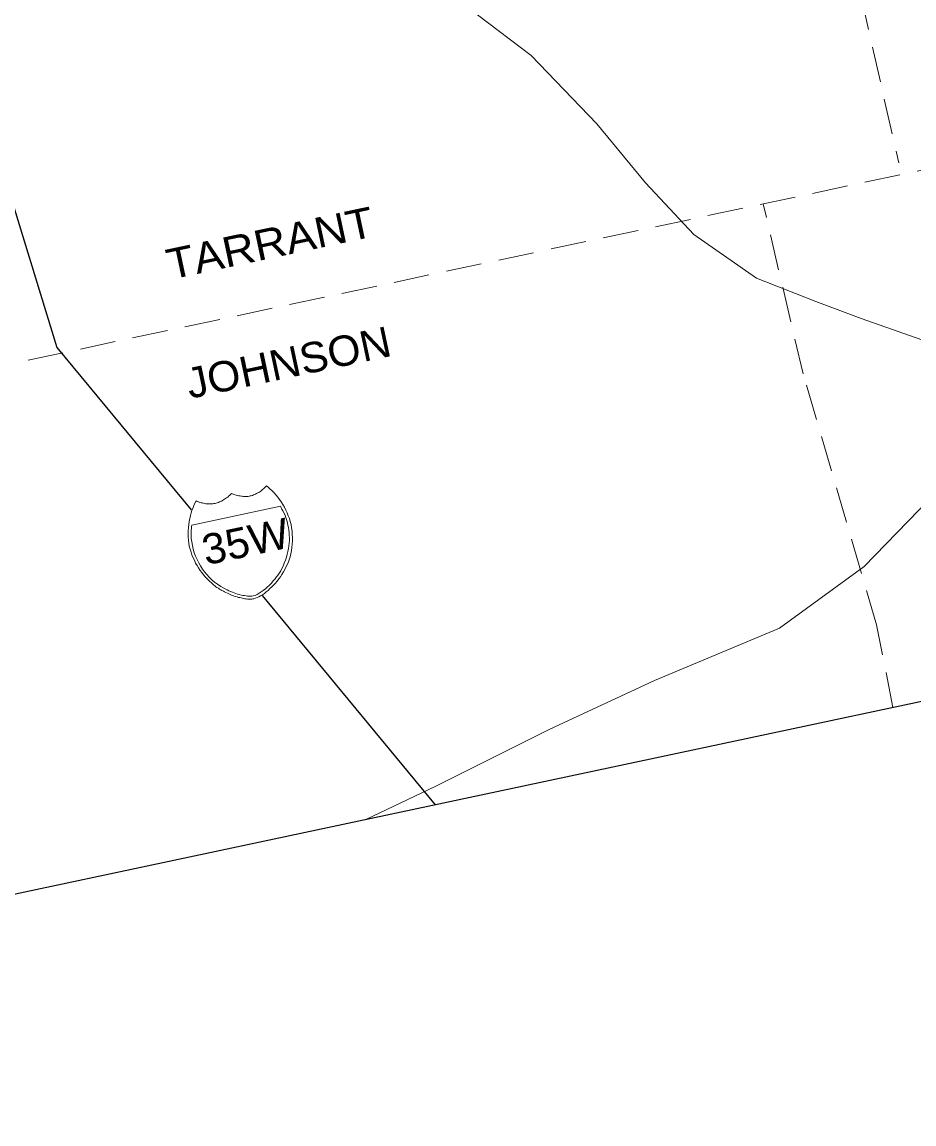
# Model space of a CAD drawing. Extents: x 2357218 to 2371708, y 6973728 to 6980157.
# Drawn here: x 2357522.9 to 2357673, y 6974407.9 to 6974593.4 of the extents above; entities that cross this region are included whole.
import ezdxf

# ---------------------------------------------------------------- set-up
doc = ezdxf.new("R2010")
doc.units = 0
doc.header["$LTSCALE"] = 2
doc.linetypes.add('MEDIUM_DASHED', pattern=[4.5, 3, -1.5])
doc.layers.add('62', color=7, linetype='Continuous', lineweight=13)
doc.layers.add('63', color=7, linetype='Continuous', lineweight=13)

msp = doc.modelspace()

# ---------------------------------------------------------------- linework, layer by layer
at = {"layer": '62', "linetype": 'MEDIUM_DASHED'}
for p, q in [((2357608.391, 6974843.78), (2357670.463, 6974569.716)), ((2357321.423, 6974493.477), (2357761.192, 6974586.953))]:
    msp.add_line(p, q, dxfattribs=at)
at = {"layer": '62', "lineweight": 25}
msp.add_line((2357563.3, 6974496.922), (2357592.436, 6974461.686), dxfattribs=at)
for points in [[(2357242.867, 6974863.05), (2357339.603, 6974407.945), (2357779.37, 6974501.42), (2357682.634, 6974956.528)], [(2357484.401, 6974709.004), (2357495.501, 6974661.441), (2357507.761, 6974607.022), (2357528.73, 6974538.67), (2357551.355, 6974511.341)]]:
    msp.add_lwpolyline(points, dxfattribs=at)
at = {"layer": '62'}
for points in [[(2357711.499, 6974538.57), (2357702.972, 6974539.842), (2357693.168, 6974539.642), (2357675.502, 6974539.523), (2357664.168, 6974543.509), (2357656.491, 6974546.383), (2357646.543, 6974550.319), (2357635.988, 6974557.671), (2357627.86, 6974566.366), (2357619.672, 6974576.31), (2357608.58, 6974587.803), (2357599.534, 6974594.644), (2357592.196, 6974601.778), (2357583.834, 6974610.927), (2357578.923, 6974614.877), (2357569.363, 6974625.866)], [(2357712.856, 6974614.337), (2357709.274, 6974604.465), (2357703.489, 6974586.211), (2357701.445, 6974566.614), (2357701.343, 6974551.94), (2357687.74, 6974535.638), (2357689.697, 6974525.767), (2357675.675, 6974513.172), (2357664.632, 6974501.808), (2357650.419, 6974491.402), (2357629.375, 6974482.602), (2357611.62, 6974474.364), (2357592.404, 6974464.761), (2357580.771, 6974459.205)], [(2357561.902, 6974496.349), (2357561.721, 6974496.335), (2357561.569, 6974496.303), (2357561.388, 6974496.286), (2357561.226, 6974496.298), (2357561.039, 6974496.305), (2357560.854, 6974496.31), (2357560.618, 6974496.331), (2357560.405, 6974496.353), (2357560.212, 6974496.404), (2357560, 6974496.429), (2357559.754, 6974496.49), (2357559.538, 6974496.536), (2357559.299, 6974496.58), (2357559.103, 6974496.65), (2357558.851, 6974496.737), (2357558.608, 6974496.801), (2357558.383, 6974496.89), (2357558.134, 6974496.976), (2357557.906, 6974497.087), (2357557.678, 6974497.176), (2357557.45, 6974497.267), (2357557.217, 6974497.402), (2357556.989, 6974497.492), (2357556.781, 6974497.609), (2357556.546, 6974497.743), (2357556.337, 6974497.859), (2357556.128, 6974497.974), (2357555.936, 6974498.118), (2357555.701, 6974498.252), (2357555.514, 6974498.372), (2357555.343, 6974498.522), (2357555.153, 6974498.665), (2357554.814, 6974498.961), (2357554.438, 6974499.32), (2357554.113, 6974499.663), (2357553.788, 6974500.009), (2357553.457, 6974500.374), (2357553.147, 6974500.745), (2357552.861, 6974501.12), (2357552.612, 6974501.53), (2357552.343, 6974501.932), (2357552.09, 6974502.361), (2357551.899, 6974502.828), (2357551.691, 6974503.266), (2357551.477, 6974503.727), (2357551.335, 6974504.181), (2357551.18, 6974504.7), (2357551.047, 6974505.2), (2357550.986, 6974505.719), (2357550.921, 6974506.234), (2357550.88, 6974506.754), (2357550.859, 6974507.279), (2357550.867, 6974507.787), (2357550.893, 6974508.321), (2357550.943, 6974508.836), (2357550.994, 6974509.354), (2357551.117, 6974509.864), (2357551.219, 6974510.346), (2357551.351, 6974510.809), (2357551.491, 6974511.232), (2357551.672, 6974511.686), (2357551.796, 6974512.076), (2357551.989, 6974512.463), (2357552.188, 6974512.828), (2357552.392, 6974512.735), (2357552.618, 6974512.644), (2357552.841, 6974512.575), (2357553.036, 6974512.524), (2357553.252, 6974512.478), (2357553.446, 6974512.429), (2357553.658, 6974512.404), (2357553.855, 6974512.355), (2357554.038, 6974512.349), (2357554.228, 6974512.319), (2357554.435, 6974512.317), (2357554.616, 6974512.331), (2357554.848, 6974512.337), (2357555.011, 6974512.323), (2357555.187, 6974512.361), (2357555.406, 6974512.408), (2357555.582, 6974512.446), (2357555.758, 6974512.483), (2357555.946, 6974512.568), (2357556.113, 6974512.65), (2357556.284, 6974512.71), (2357556.451, 6974512.792), (2357556.658, 6974512.905), (2357556.827, 6974512.985), (2357556.984, 6974513.112), (2357557.146, 6974513.216), (2357557.325, 6974513.346), (2357557.503, 6974513.476), (2357557.661, 6974513.601), (2357557.814, 6974513.747), (2357557.964, 6974513.917), (2357558.131, 6974514.091), (2357558.335, 6974513.998), (2357558.539, 6974513.902), (2357558.762, 6974513.835), (2357558.955, 6974513.784)], [(2357558.955, 6974513.784), (2357559.152, 6974513.732), (2357559.368, 6974513.686), (2357559.537, 6974513.654), (2357559.753, 6974513.608), (2357559.96, 6974513.605), (2357560.15, 6974513.578), (2357560.335, 6974513.572), (2357560.538, 6974513.591), (2357560.723, 6974513.585), (2357560.932, 6974513.583), (2357561.108, 6974513.62), (2357561.308, 6974513.663), (2357561.482, 6974513.699), (2357561.656, 6974513.737), (2357561.867, 6974513.829), (2357562.013, 6974513.904), (2357562.184, 6974513.965), (2357562.373, 6974514.049), (2357562.558, 6974514.159), (2357562.725, 6974514.24), (2357562.904, 6974514.369), (2357563.066, 6974514.472), (2357563.223, 6974514.597), (2357563.381, 6974514.723), (2357563.538, 6974514.848), (2357563.712, 6974515.002), (2357563.881, 6974515.177), (2357564.031, 6974515.346), (2357564.359, 6974515.094), (2357564.673, 6974514.816), (2357564.989, 6974514.515), (2357565.314, 6974514.17), (2357565.616, 6974513.842), (2357565.924, 6974513.471), (2357566.218, 6974513.073), (2357566.514, 6974512.652), (2357566.792, 6974512.207), (2357567.05, 6974511.755), (2357567.287, 6974511.276), (2357567.501, 6974510.816), (2357567.697, 6974510.328), (2357567.892, 6974509.84), (2357568.023, 6974509.339), (2357568.176, 6974508.841), (2357568.248, 6974508.282), (2357568.342, 6974507.725), (2357568.373, 6974507.157), (2357568.412, 6974506.636), (2357568.438, 6974506.09), (2357568.374, 6974505.524), (2357568.328, 6974504.984), (2357568.254, 6974504.464), (2357568.136, 6974503.931), (2357567.998, 6974503.397), (2357567.828, 6974502.899), (2357567.66, 6974502.381), (2357567.425, 6974501.871), (2357567.181, 6974501.384), (2357566.92, 6974500.888), (2357566.607, 6974500.41), (2357566.387, 6974500.041), (2357566.14, 6974499.69), (2357565.847, 6974499.328), (2357565.573, 6974498.994), (2357565.25, 6974498.673), (2357564.926, 6974498.35), (2357564.621, 6974498.055), (2357564.318, 6974497.761), (2357564.007, 6974497.489), (2357563.689, 6974497.257), (2357563.369, 6974497.03), (2357563.047, 6974496.822), (2357562.755, 6974496.668), (2357562.461, 6974496.538), (2357562.161, 6974496.429), (2357561.902, 6974496.349)]]:
    msp.add_lwpolyline(points, dxfattribs=at)
at = {"layer": '62', "linetype": 'MEDIUM_DASHED'}
msp.add_lwpolyline([(2357669.497, 6974478.065), (2357666.726, 6974491.968), (2357654.36, 6974534.223), (2357647.638, 6974562.817)], dxfattribs=at)
at = {"layer": '62'}
msp.add_lwpolyline([(2357566.373, 6974511.911), (2357551.47, 6974508.742), (2357551.43, 6974508.504), (2357551.401, 6974508.2), (2357551.378, 6974507.874), (2357551.375, 6974507.456), (2357551.359, 6974506.993), (2357551.378, 6974506.469), (2357551.446, 6974505.931), (2357551.575, 6974505.312), (2357551.705, 6974504.72), (2357551.884, 6974504.088), (2357552.098, 6974503.514), (2357552.356, 6974502.947), (2357552.637, 6974502.386), (2357552.93, 6974501.873), (2357553.249, 6974501.343), (2357553.625, 6974500.871), (2357553.997, 6974500.421), (2357554.392, 6974499.976), (2357554.852, 6974499.544), (2357555.305, 6974499.135), (2357555.817, 6974498.785), (2357556.351, 6974498.435), (2357556.876, 6974498.133), (2357557.445, 6974497.842), (2357557.706, 6974497.689), (2357558.003, 6974497.59), (2357558.288, 6974497.444), (2357558.606, 6974497.351), (2357558.884, 6974497.248), (2357559.183, 6974497.13), (2357559.47, 6974497.076), (2357559.767, 6974496.978), (2357560.055, 6974496.922), (2357560.316, 6974496.888), (2357560.605, 6974496.833), (2357560.843, 6974496.791), (2357561.12, 6974496.781), (2357561.35, 6974496.785), (2357561.575, 6974496.81), (2357561.801, 6974496.836), (2357562.106, 6974496.923), (2357562.463, 6974497.066), (2357562.788, 6974497.273), (2357563.156, 6974497.492), (2357563.495, 6974497.723), (2357563.85, 6974498.007), (2357564.179, 6974498.306), (2357564.523, 6974498.631), (2357564.864, 6974498.981), (2357565.177, 6974499.346), (2357565.473, 6974499.684), (2357565.747, 6974500.019), (2357566.022, 6974500.353), (2357566.247, 6974500.7), (2357566.45, 6974501.044), (2357566.574, 6974501.323), (2357566.828, 6974501.861), (2357567.02, 6974502.361), (2357567.213, 6974502.86), (2357567.379, 6974503.378), (2357567.532, 6974503.85), (2357567.64, 6974504.333), (2357567.725, 6974504.787), (2357567.786, 6974505.26), (2357567.85, 6974505.711), (2357567.894, 6974506.156), (2357567.895, 6974506.596), (2357567.866, 6974507.048), (2357567.842, 6974507.481), (2357567.798, 6974507.908), (2357567.73, 6974508.334), (2357567.646, 6974508.728), (2357567.515, 6974509.347), (2357567.36, 6974509.864), (2357567.164, 6974510.354), (2357567.004, 6974510.778), (2357566.81, 6974511.152), (2357566.633, 6974511.437), (2357566.484, 6974511.704)], close=True, dxfattribs=at)
at = {"layer": '63', "linetype": 'MEDIUM_DASHED'}
for p, q in [((2357608.391, 6974843.78), (2357670.463, 6974569.716)), ((2357321.423, 6974493.477), (2357761.192, 6974586.953))]:
    msp.add_line(p, q, dxfattribs=at)
at = {"layer": '63', "lineweight": 25}
msp.add_line((2357563.3, 6974496.922), (2357592.436, 6974461.686), dxfattribs=at)
for points in [[(2357242.867, 6974863.05), (2357339.603, 6974407.945), (2357779.37, 6974501.42), (2357682.634, 6974956.528)], [(2357484.401, 6974709.004), (2357495.501, 6974661.441), (2357507.761, 6974607.022), (2357528.73, 6974538.67), (2357551.355, 6974511.341)]]:
    msp.add_lwpolyline(points, dxfattribs=at)
at = {"layer": '63'}
for points in [[(2357711.499, 6974538.57), (2357702.972, 6974539.842), (2357693.168, 6974539.642), (2357675.502, 6974539.523), (2357664.168, 6974543.509), (2357656.491, 6974546.383), (2357646.543, 6974550.319), (2357635.988, 6974557.671), (2357627.86, 6974566.366), (2357619.672, 6974576.31), (2357608.58, 6974587.803), (2357599.534, 6974594.644), (2357592.196, 6974601.778), (2357583.834, 6974610.927), (2357578.923, 6974614.877), (2357569.363, 6974625.866)], [(2357712.856, 6974614.337), (2357709.274, 6974604.465), (2357703.489, 6974586.211), (2357701.445, 6974566.614), (2357701.343, 6974551.94), (2357687.74, 6974535.638), (2357689.697, 6974525.767), (2357675.675, 6974513.172), (2357664.632, 6974501.808), (2357650.419, 6974491.402), (2357629.375, 6974482.602), (2357611.62, 6974474.364), (2357592.404, 6974464.761), (2357580.771, 6974459.205)], [(2357561.902, 6974496.349), (2357561.721, 6974496.335), (2357561.569, 6974496.303), (2357561.388, 6974496.286), (2357561.226, 6974496.298), (2357561.039, 6974496.305), (2357560.854, 6974496.31), (2357560.618, 6974496.331), (2357560.405, 6974496.353), (2357560.212, 6974496.404), (2357560, 6974496.429), (2357559.754, 6974496.49), (2357559.538, 6974496.536), (2357559.299, 6974496.58), (2357559.103, 6974496.65), (2357558.851, 6974496.737), (2357558.608, 6974496.801), (2357558.383, 6974496.89), (2357558.134, 6974496.976), (2357557.906, 6974497.087), (2357557.678, 6974497.176), (2357557.45, 6974497.267), (2357557.217, 6974497.402), (2357556.989, 6974497.492), (2357556.781, 6974497.609), (2357556.546, 6974497.743), (2357556.337, 6974497.859), (2357556.128, 6974497.974), (2357555.936, 6974498.118), (2357555.701, 6974498.252), (2357555.514, 6974498.372), (2357555.343, 6974498.522), (2357555.153, 6974498.665), (2357554.814, 6974498.961), (2357554.438, 6974499.32), (2357554.113, 6974499.663), (2357553.788, 6974500.009), (2357553.457, 6974500.374), (2357553.147, 6974500.745), (2357552.861, 6974501.12), (2357552.612, 6974501.53), (2357552.343, 6974501.932), (2357552.09, 6974502.361), (2357551.899, 6974502.828), (2357551.691, 6974503.266), (2357551.477, 6974503.727), (2357551.335, 6974504.181), (2357551.18, 6974504.7), (2357551.047, 6974505.2), (2357550.986, 6974505.719), (2357550.921, 6974506.234), (2357550.88, 6974506.754), (2357550.859, 6974507.279), (2357550.867, 6974507.787), (2357550.893, 6974508.321), (2357550.943, 6974508.836), (2357550.994, 6974509.354), (2357551.117, 6974509.864), (2357551.219, 6974510.346), (2357551.351, 6974510.809), (2357551.491, 6974511.232), (2357551.672, 6974511.686), (2357551.796, 6974512.076), (2357551.989, 6974512.463), (2357552.188, 6974512.828), (2357552.392, 6974512.735), (2357552.618, 6974512.644), (2357552.841, 6974512.575), (2357553.036, 6974512.524), (2357553.252, 6974512.478), (2357553.446, 6974512.429), (2357553.658, 6974512.404), (2357553.855, 6974512.355), (2357554.038, 6974512.349), (2357554.228, 6974512.319), (2357554.435, 6974512.317), (2357554.616, 6974512.331), (2357554.848, 6974512.337), (2357555.011, 6974512.323), (2357555.187, 6974512.361), (2357555.406, 6974512.408), (2357555.582, 6974512.446), (2357555.758, 6974512.483), (2357555.946, 6974512.568), (2357556.113, 6974512.65), (2357556.284, 6974512.71), (2357556.451, 6974512.792), (2357556.658, 6974512.905), (2357556.827, 6974512.985), (2357556.984, 6974513.112), (2357557.146, 6974513.216), (2357557.325, 6974513.346), (2357557.503, 6974513.476), (2357557.661, 6974513.601), (2357557.814, 6974513.747), (2357557.964, 6974513.917), (2357558.131, 6974514.091), (2357558.335, 6974513.998), (2357558.539, 6974513.902), (2357558.762, 6974513.835), (2357558.955, 6974513.784)], [(2357558.955, 6974513.784), (2357559.152, 6974513.732), (2357559.368, 6974513.686), (2357559.537, 6974513.654), (2357559.753, 6974513.608), (2357559.96, 6974513.605), (2357560.15, 6974513.578), (2357560.335, 6974513.572), (2357560.538, 6974513.591), (2357560.723, 6974513.585), (2357560.932, 6974513.583), (2357561.108, 6974513.62), (2357561.308, 6974513.663), (2357561.482, 6974513.699), (2357561.656, 6974513.737), (2357561.867, 6974513.829), (2357562.013, 6974513.904), (2357562.184, 6974513.965), (2357562.373, 6974514.049), (2357562.558, 6974514.159), (2357562.725, 6974514.24), (2357562.904, 6974514.369), (2357563.066, 6974514.472), (2357563.223, 6974514.597), (2357563.381, 6974514.723), (2357563.538, 6974514.848), (2357563.712, 6974515.002), (2357563.881, 6974515.177), (2357564.031, 6974515.346), (2357564.359, 6974515.094), (2357564.673, 6974514.816), (2357564.989, 6974514.515), (2357565.314, 6974514.17), (2357565.616, 6974513.842), (2357565.924, 6974513.471), (2357566.218, 6974513.073), (2357566.514, 6974512.652), (2357566.792, 6974512.207), (2357567.05, 6974511.755), (2357567.287, 6974511.276), (2357567.501, 6974510.816), (2357567.697, 6974510.328), (2357567.892, 6974509.84), (2357568.023, 6974509.339), (2357568.176, 6974508.841), (2357568.248, 6974508.282), (2357568.342, 6974507.725), (2357568.373, 6974507.157), (2357568.412, 6974506.636), (2357568.438, 6974506.09), (2357568.374, 6974505.524), (2357568.328, 6974504.984), (2357568.254, 6974504.464), (2357568.136, 6974503.931), (2357567.998, 6974503.397), (2357567.828, 6974502.899), (2357567.66, 6974502.381), (2357567.425, 6974501.871), (2357567.181, 6974501.384), (2357566.92, 6974500.888), (2357566.607, 6974500.41), (2357566.387, 6974500.041), (2357566.14, 6974499.69), (2357565.847, 6974499.328), (2357565.573, 6974498.994), (2357565.25, 6974498.673), (2357564.926, 6974498.35), (2357564.621, 6974498.055), (2357564.318, 6974497.761), (2357564.007, 6974497.489), (2357563.689, 6974497.257), (2357563.369, 6974497.03), (2357563.047, 6974496.822), (2357562.755, 6974496.668), (2357562.461, 6974496.538), (2357562.161, 6974496.429), (2357561.902, 6974496.349)]]:
    msp.add_lwpolyline(points, dxfattribs=at)
at = {"layer": '63', "linetype": 'MEDIUM_DASHED'}
msp.add_lwpolyline([(2357669.497, 6974478.065), (2357666.726, 6974491.968), (2357654.36, 6974534.223), (2357647.638, 6974562.817)], dxfattribs=at)
at = {"layer": '63'}
msp.add_lwpolyline([(2357566.373, 6974511.911), (2357551.47, 6974508.742), (2357551.43, 6974508.504), (2357551.401, 6974508.2), (2357551.378, 6974507.874), (2357551.375, 6974507.456), (2357551.359, 6974506.993), (2357551.378, 6974506.469), (2357551.446, 6974505.931), (2357551.575, 6974505.312), (2357551.705, 6974504.72), (2357551.884, 6974504.088), (2357552.098, 6974503.514), (2357552.356, 6974502.947), (2357552.637, 6974502.386), (2357552.93, 6974501.873), (2357553.249, 6974501.343), (2357553.625, 6974500.871), (2357553.997, 6974500.421), (2357554.392, 6974499.976), (2357554.852, 6974499.544), (2357555.305, 6974499.135), (2357555.817, 6974498.785), (2357556.351, 6974498.435), (2357556.876, 6974498.133), (2357557.445, 6974497.842), (2357557.706, 6974497.689), (2357558.003, 6974497.59), (2357558.288, 6974497.444), (2357558.606, 6974497.351), (2357558.884, 6974497.248), (2357559.183, 6974497.13), (2357559.47, 6974497.076), (2357559.767, 6974496.978), (2357560.055, 6974496.922), (2357560.316, 6974496.888), (2357560.605, 6974496.833), (2357560.843, 6974496.791), (2357561.12, 6974496.781), (2357561.35, 6974496.785), (2357561.575, 6974496.81), (2357561.801, 6974496.836), (2357562.106, 6974496.923), (2357562.463, 6974497.066), (2357562.788, 6974497.273), (2357563.156, 6974497.492), (2357563.495, 6974497.723), (2357563.85, 6974498.007), (2357564.179, 6974498.306), (2357564.523, 6974498.631), (2357564.864, 6974498.981), (2357565.177, 6974499.346), (2357565.473, 6974499.684), (2357565.747, 6974500.019), (2357566.022, 6974500.353), (2357566.247, 6974500.7), (2357566.45, 6974501.044), (2357566.574, 6974501.323), (2357566.828, 6974501.861), (2357567.02, 6974502.361), (2357567.213, 6974502.86), (2357567.379, 6974503.378), (2357567.532, 6974503.85), (2357567.64, 6974504.333), (2357567.725, 6974504.787), (2357567.786, 6974505.26), (2357567.85, 6974505.711), (2357567.894, 6974506.156), (2357567.895, 6974506.596), (2357567.866, 6974507.048), (2357567.842, 6974507.481), (2357567.798, 6974507.908), (2357567.73, 6974508.334), (2357567.646, 6974508.728), (2357567.515, 6974509.347), (2357567.36, 6974509.864), (2357567.164, 6974510.354), (2357567.004, 6974510.778), (2357566.81, 6974511.152), (2357566.633, 6974511.437), (2357566.484, 6974511.704)], close=True, dxfattribs=at)

# ---------------------------------------------------------------- texts
at = {"layer": '62'}
for s, width, p in [('TARRANT', 1.1, (2357547.841, 6974550.047)), ('JOHNSON', 1.05, (2357551.138, 6974529.996)), ('35W', 1.05, (2357553.829, 6974501.971))]:
    msp.add_text(s, height=5.099, rotation=12, dxfattribs=dict(at, width=width)).set_placement(p)
at = {"layer": '63'}
for s, width, p in [('TARRANT', 1.1, (2357547.841, 6974550.047)), ('JOHNSON', 1.05, (2357551.138, 6974529.996)), ('35W', 1.05, (2357553.829, 6974501.971))]:
    msp.add_text(s, height=5.099, rotation=12, dxfattribs=dict(at, width=width)).set_placement(p)

doc.saveas('drawing.dxf')
